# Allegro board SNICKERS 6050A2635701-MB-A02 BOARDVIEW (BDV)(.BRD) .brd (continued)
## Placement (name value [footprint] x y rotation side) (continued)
C6203  22uF_6.3V_5  [CSC_200X125X130_2]  167.19 155.16 0 bottom
C6204  22uF_6.3V_5_DY  [CSC_200X125X130_2]  167.2 156.78 0 bottom
C6210  10UF_25V_5  [CSC_200X125X140_2]  150.15 160.51 270 bottom
C6211  0.1uF_25V_2  [CSC_100X050X040_2]  151.42 160.89 270 bottom
C6215  0.1uF_16V_2  [CSC_100X050X040_2]  156.5 154.29 270 bottom
C6216  1uF_6.3V_2  [CSC_100X050X040_2]  154.08 156.32 90 bottom
C6217  0.01uF_50V_2  [CSC_100X050X040_2]  153.19 156.32 90 bottom
C6240  10uF_6.3V_3  [CSC_160X080X080_2]  171.1 155.94 90 bottom
C6241  10uF_6.3V_3  [CSC_160X080X080_2]  172.14 150.11 270 bottom
C6242  1uF_6.3V_2  [CSC_100X050X040_2]  176.44 150.62 180 bottom
C6243  1uF_6.3V_2  [CSC_100X050X040_2]  175.67 155.05 180 bottom
C6300  22uF_6.3V_5  [CSC_200X125X130_2]  137.32 96.43 0 bottom
C6301  22uF_6.3V_5  [CSC_200X125X130_2]  137.32 93.23 0 bottom
C6302  22uF_6.3V_5  [CSC_200X125X130_2]  137.32 94.83 0 bottom
C6303  22uF_6.3V_5  [CSC_200X125X130_2]  137.32 98.03 0 bottom
C6304  22uF_6.3V_5_DY  [CSC_200X125X130_2]  137.32 99.63 0 bottom
C6310  10UF_25V_5  [CSC_200X125X140_2]  126.5 101.71 0 bottom
C6311  0.1uF_25V_2  [CSC_100X050X040_2]  126.27 102.98 0 bottom
C6315  0.1uF_16V_2  [CSC_100X050X040_2]  127.67 94.6 90 bottom
C6316  1uF_6.3V_2  [CSC_100X050X040_2]  123.6 94.73 90 bottom
C6317  0.01uF_50V_2  [CSC_100X050X040_2]  122.71 94.73 90 bottom
C6350  22uF_6.3V_5  [CSC_200X125X130_2]  103.28 135.75 270 bottom
C6352  CSC0402_DY  [CSC_100X050X040_2]  103.92 143.5 180 top
C6360  10uF_6.3V_3  [CSC_160X080X080_2]  101.25 147.69 180 top
C6450  22uF_6.3V_5  [CSC_200X125X130_2]  254.41 84.06 180 top
C6452  CSC0402_DY  [CSC_100X050X040_2]  246.54 82.54 90 top
C6460  10uF_6.3V_3  [CSC_160X080X080_2]  249.33 82.79 270 top
C6610  10UF_25V_5  [CSC_200X125X140_2]  238.28 71.74 180 bottom
C6611  10UF_25V_5  [CSC_200X125X140_2]  238.28 73.39 180 bottom
C6613  CSC0402_DY  [CSC_100X050X040_2]  223.3 78.32 270 bottom
C6614  CSC0402_DY  [CSC_100X050X040_2]  223.3 79.97 90 bottom
C6615  0.1uF_16V_2  [CSC_100X050X040_2]  240.44 65.64 180 bottom
C6616  1uF_10V_2  [CSC_100X050X040_2]  234.73 64.12 180 bottom
C6617  0.1uF_25V_2  [CSC_100X050X040_2]  226.98 78.98 90 bottom
C6618  CSC0402_DY  [CSC_100X050X040_2]  226.09 78.98 90 bottom
C6639  0.0015uF_50V_2  [CSC_100X050X040_2]  226.09 85.58 270 bottom
C6640  CSC0402_DY  [CSC_100X050X040_2]  227.77 82.94 0 bottom
C6641  CSC0402_DY  [CSC_100X050X040_2]  230.28 86.85 90 bottom
C6642  1uF_6.3V_2  [CSC_100X050X040_2]  233.82 81.52 0 bottom
C6643  1uF_6.3V_2  [CSC_100X050X040_2]  228.38 86.85 90 bottom
C6644  0.33uF_10V_3  [CSC_160X080X080_2]  228.89 82.66 0 top
C6645  4700pF_50V_2  [CSC_100X050X040_2]  229.78 74.15 270 bottom
C6646  1000PF_50V_2  [CSC_100X050X055_2]  228.51 76.06 0 bottom
C6699  15uF_25V  [CS_350X280X200_2]  244.13 77.96 0 bottom
C6900  0.22uF_6.3V_2  [CSC_100X050X040_2]  283.12 131.68 90 top
C6902  3900pF_16V_2  [CSC_100X050X040_2]  65.82 89.65 90 top
C6906  CSC0402_DY  [CSC_100X050X040_2]  294.67 137.53 270 top
C6998  0.22uF_6.3V_2  [CSC_100X050X040_2]  293.02 128.64 270 top
C6999  100pF_50V_2  [CSC_100X050X040_2]  294.04 133.21 90 top
C7001  1uF_6.3V_2  [CSC_100X050X040_2]  301.28 127.37 270 top
C7035  CSC0402_DY  [CSC_100X050X040_2]  97.44 143.24 180 top
C7036  CSC0402_DY  [CSC_100X050X040_2]  210.22 147.18 90 top
C7037  CSC0402_DY  [CSC_100X050X040_2]  117.13 96 90 top
C7050  10uF_6.3V_3  [CSC_160X080X080_2]  117.25 83.68 270 bottom
C7100  10uF_6.3V_3  [CSC_160X080X080_2]  303.31 109.59 0 top
C7110  0.1uF_16V_2  [CSC_100X050X040_2]  211.11 149.97 90 bottom
C7152  CSC0402_DY  [CSC_100X050X040_2]  139.73 103.62 180 bottom
C7153  10uF_6.3V_3  [CSC_160X080X080_2]  136.43 91.17 90 bottom
C7352  10uF_6.3V_3  [CSC_160X080X080_2]  109.38 84.69 270 bottom
C7355  10uF_6.3V_3  [CSC_160X080X080_2]  307.25 115.94 90 top
C7400  0.1uF_16V_2  [CSC_100X050X040_2]  239.94 109.97 90 top
C7401  3300pF_50V_2  [CSC_100X050X040_2]  243.24 100.44 90 top
C7402  1000PF_50V_2  [CSC_100X050X055_2]  241.41 100.44 90 top
C7403  3300pF_50V_2  [CSC_100X050X040_2]  243.24 112.25 90 top
C7455  82pF_50V_2  [CSC_100X050X040_2]  116.87 126.48 0 top
C7456  0.1uF_25V_2  [CSC_100X050X040_2]  116.87 125.46 0 top
C7457  68pF_50V_2_DY  [CSC_100X050X040_2]  274.23 118.48 180 top
C7458  82pF_50V_2  [CSC_100X050X040_2]  274.23 117.59 180 top
C7459  68pF_50V_2_DY  [CSC_100X050X040_2]  195.23 60.82 0 top
C7460  82pF_50V_2_DY  [CSC_100X050X040_2]  195.87 59.93 0 top
C7461  68pF_50V_2_DY  [CSC_100X050X040_2]  224.57 54.47 90 top
C7462  82pF_50V_2_DY  [CSC_100X050X040_2]  225.46 54.47 90 top
C7463  68pF_50V_2_DY  [CSC_100X050X040_2]  223.81 68.57 270 top
C7464  82pF_50V_2_DY  [CSC_100X050X040_2]  222.92 68.57 270 top
C7465  68pF_50V_2_DY  [CSC_100X050X040_2]  196.37 67.8 0 bottom
C7466  82pF_50V_2_DY  [CSC_100X050X040_2]  196.37 68.69 0 bottom
C7467  68pF_50V_2  [CSC_100X050X040_2]  256.95 144.89 180 top
C7468  82pF_50V_2  [CSC_100X050X040_2]  142.65 160.64 0 top
C7469  68pF_50V_2_DY  [CSC_100X050X040_2]  162.34 158.86 0 bottom
C7470  82pF_50V_2_DY  [CSC_100X050X040_2]  168.69 150.61 180 bottom
C7471  68pF_50V_2_DY  [CSC_100X050X040_2]  136.68 101.33 270 bottom
C7472  68pF_50V_2  [CSC_100X050X040_2]  118.65 99.05 90 bottom
C7473  82pF_50V_2  [CSC_100X050X040_2]  119.54 99.43 90 bottom
C7474  82pF_50V_2_DY  [CSC_100X050X040_2]  135.67 101.33 270 bottom
C7475  CSC0402_DY  [CSC_100X050X040_2]  156.62 86.73 90 bottom
C7476  CSC0402_DY  [CSC_100X050X040_2]  163.35 106.69 90 top
C7478  CSC0402_DY  [CSC_100X050X040_2]  162.47 106.69 90 top
C7485  4.7uF_6.3V_3_DY  [CSC_160X080X080_2]  126.65 130.8 0 top
C7486  4.7uF_6.3V_3_DY  [CSC_160X080X080_2]  169.32 148.7 180 bottom
C7487  2.2uF_6.3V_2  [CSC_100X050X040_2]  169.32 149.72 0 bottom
C7488  CSC0402_DY  [CSC_100X050X040_2]  173.51 85.2 90 top
C7490  82pF_50V_2  [CSC_100X050X040_2]  213.52 156.96 90 bottom
C7491  82pF_50V_2  [CSC_100X050X040_2]  249.97 149.08 180 bottom
C7494  2.2uF_6.3V_2_DY  [CSC_100X050X040_2]  173.51 56.12 180 top
C7495  82pF_50V_2  [CSC_100X050X040_2]  239.55 78.47 90 bottom
C7500  100pF_50V_2  [CSC_100X050X040_2]  155.38 63.74 180 bottom
C7501  100pF_50V_2  [CSC_100X050X040_2]  155.25 66.41 180 bottom
C7502  0.1uF_25V_2  [CSC_100X050X040_2]  137.07 65.14 180 top
C7503  100pF_50V_2  [CSC_100X050X040_2]  147.23 65.26 90 bottom
C7520  0.1uF_16V_2  [CSC_100X050X040_2]  314.23 82.15 270 top
C7521  0.1uF_16V_2  [CSC_100X050X040_2]  320.58 117.71 180 top
C7578  0.1uF_16V_2  [CSC_100X050X040_2]  315.37 16.37 90 top
C7579  0.1uF_16V_2  [CSC_100X050X040_2]  294.67 56.63 90 bottom
C7581  0.1uF_16V_2_DY  [CSC_100X050X040_2]  116.49 124.19 180 top
C7582  82pF_50V_2  [CSC_100X050X040_2]  142.65 152.56 180 top
C7583  0.1uF_16V_2_DY  [CSC_100X050X040_2]  132.37 113.4 180 top
C7584  0.1uF_16V_2_DY  [CSC_100X050X040_2]  156.62 77.33 90 top
C7585  0.1uF_16V_2_DY  [CSC_100X050X040_2]  239.3 63.87 270 top
C7586  0.1uF_16V_2_DY  [CSC_100X050X040_2]  228.12 96 180 top
C7587  0.1uF_16V_2_DY  [CSC_100X050X040_2]  281.21 123.43 90 top
C7588  0.1uF_16V_2_DY  [CSC_100X050X040_2]  245.65 56.37 270 bottom
C7589  0.1uF_16V_2_DY  [CSC_100X050X040_2]  303.3 110.62 0 top
C7591  0.1uF_16V_2_DY  [CSC_100X050X040_2]  180.37 82.79 0 top
C7592  0.1uF_16V_2_DY  [CSC_100X050X040_2]  316.59 21.45 270 top
C7593  0.1uF_16V_2_DY  [CSC_100X050X040_2]  289.21 93.08 270 top
C7594  82pF_50V_2  [CSC_100X050X040_2]  245.52 83.04 270 top
C7595  0.1uF_25V_2_DY  [CSC_100X050X040_2]  144.69 160.13 90 bottom
C7596  0.1uF_16V_2_DY  [CSC_100X050X040_2]  143.16 65.26 270 bottom
C7597  0.1uF_16V_2  [CSC_100X050X040_2]  218.73 144.64 0 bottom
C7598  0.1uF_16V_2  [CSC_100X050X040_2]  240.95 140.83 0 top
C7599  82pF_50V_2  [CSC_100X050X040_2]  248.83 146.16 0 bottom
C7600  CSC0402_DY  [CSC_100X050X040_2]  269.15 132.32 90 bottom
C7601  0.1uF_25V_2  [CSC_100X050X040_2]  269.91 115.43 180 top
C7602  0.1uF_25V_2  [CSC_100X050X040_2]  208.69 157.47 180 bottom
C7603  0.1uF_25V_2  [CSC_100X050X040_2]  125.38 113.78 0 top
C7604  0.1uF_16V_2  [CSC_100X050X040_2]  199.93 126.35 0 top
C7605  0.1uF_16V_2  [CSC_100X050X040_2]  143.8 133.46 180 top
C7606  0.1uF_16V_2  [CSC_100X050X040_2]  163.23 149.59 90 bottom
C7607  0.1uF_16V_2_DY  [CSC_100X050X040_2]  170.44 53.33 270 top
C7608  0.1uF_16V_2_DY  [CSC_100X050X040_2]  109.76 88.89 180 bottom
C7609  0.1uF_25V_2_DY  [CSC_100X050X040_2]  136.81 68.44 180 top
C7610  CSC0402_DY  [CSC_100X050X040_2]  197.26 159.88 180 bottom
C7611  0.1uF_25V_2_DY  [CSC_100X050X040_2]  129.7 112.76 90 top
C7612  0.1uF_16V_2_DY  [CSC_100X050X040_2]  188.63 74.28 180 top
C7613  0.1uF_16V_2_DY  [CSC_100X050X040_2]  315.63 73.14 270 top
C7614  0.1uF_16V_2_DY  [CSC_100X050X040_2]  308.39 116.7 90 top
C7615  CSC0402_DY  [CSC_100X050X040_2]  238.28 159.12 180 bottom
C7616  0.1uF_25V_2_DY  [CSC_100X050X040_2]  310.17 131.94 180 top
C7617  0.1uF_16V_2_DY  [CSC_100X050X040_2]  58.2 80.76 0 top
C7618  0.1uF_25V_2_DY  [CSC_100X050X040_2]  130.21 155.43 270 bottom
C7619  0.1uF_25V_2_DY  [CSC_100X050X040_2]  214.41 156.96 270 bottom
C7620  CSC0402_DY  [CSC_100X050X040_2]  155.23 150.48 180 bottom
C7621  0.1uF_25V_2  [CSC_100X050X040_2]  278.42 146.29 180 top
C7622  0.1uF_16V_2_DY  [CSC_100X050X040_2]  212 63.87 90 bottom
C7623  0.1uF_16V_2_DY  [CSC_100X050X040_2]  101.12 104.13 180 top
C7625  82pF_50V_2  [CSC_100X050X040_2]  187.1 162.04 0 top
C7627  0.1uF_16V_2  [CSC_100X050X040_2]  317.28 59.68 90 top
C7628  0.1uF_16V_2  [CSC_100X050X040_2]  316.01 38.47 0 top
C7629  0.1uF_16V_2  [CSC_100X050X040_2]  316.77 77.58 180 top
C7630  CSC0402_DY  [CSC_100X050X040_2]  133.26 101.84 0 bottom
C7631  0.1uF_16V_2  [CSC_100X050X040_2]  316.14 42.91 180 top
C7632  0.22uF_6.3V_2  [CSC_100X050X040_2]  225.2 130.67 270 top
C7633  0.22uF_6.3V_2  [CSC_100X050X040_2]  232.57 130.67 270 top
C7634  0.22uF_6.3V_2  [CSC_100X050X040_2]  213.52 144.77 270 top
C7635  0.22uF_6.3V_2  [CSC_100X050X040_2]  203.49 145.02 0 top
C7636  0.22uF_6.3V_2  [CSC_100X050X040_2]  184.06 145.15 180 top
C7637  0.22uF_6.3V_2  [CSC_100X050X040_2]  174.02 143.62 0 top
C7638  0.22uF_6.3V_2  [CSC_100X050X040_2]  147.99 146.29 180 top
C7639  0.22uF_6.3V_2  [CSC_100X050X040_2]  162.47 135.24 90 top
C7640  0.22uF_6.3V_2  [CSC_100X050X040_2]  149.13 135.62 90 top
C7641  0.1uF_25V_2  [CSC_100X050X040_2]  249.97 105.78 90 top
C7642  0.1uF_25V_2  [CSC_100X050X040_2]  238.28 78.47 270 bottom
C7643  0.1uF_25V_2  [CSC_100X050X040_2]  238.28 70.47 180 bottom
C7650  0.1uF_25V_2  [CSC_100X050X040_2]  275.37 115.17 0 bottom
C7654  CSC0402_DY  [CSC_100X050X040_2]  296.2 65.64 90 top
C7661  CSC0402_DY  [CSC_100X050X040_2]  231.93 66.53 270 top
C9000  0.1uF_16V_2  [CSC_100X050X040_2]  79.66 110.22 0 top
C9001  1uF_6.3V_2  [CSC_100X050X040_2]  79.66 111.11 0 top
C9002  0.1uF_16V_2  [CSC_100X050X040_2]  79.66 112.38 0 top
C9003  1uF_6.3V_2  [CSC_100X050X040_2]  79.66 113.27 0 top
C9004  1uF_6.3V_2  [CSC_100X050X040_2]  79.66 109.33 0 top
C9005  0.1uF_16V_2  [CSC_100X050X040_2]  79.66 114.16 0 top
C9006  0.1uF_16V_2  [CSC_100X050X040_2]  66.96 112.38 180 top
C9007  0.1uF_16V_2  [CSC_100X050X040_2]  79.66 115.56 0 top
C9009  1uF_6.3V_2  [CSC_100X050X040_2]  79.66 116.44 0 top
C9010  0.1uF_16V_2  [CSC_100X050X040_2]  75.72 120.13 90 top
C9011  1uF_6.3V_2  [CSC_100X050X040_2]  72.42 120.13 90 top
C9015  0.1uF_16V_2  [CSC_100X050X040_2]  71.53 136.64 0 top
C9021  1000PF_50V_2  [CSC_100X050X055_2]  71.79 143.5 0 top
C9035  1uF_6.3V_2  [CSC_100X050X040_2]  87.41 147.69 270 top
C9036  0.1uF_16V_2  [CSC_100X050X040_2]  73.82 157.97 270 top
C9113  0.1uF_16V_2  [CSC_100X050X040_2]  279.94 32.3 270 bottom
C9114  CSC0402_DY  [CSC_100X050X040_2]  286.67 118.73 0 top
CN200  ACES_51540_04041_001_40P  [FPC_ACES_40_050_R_180_1]  109.3 86.85 0 top
CN202  ENTERY_6712K_F08M_02L_8P  [SWBACK-6012B0275004-003]  191.05 56 0 top
CN290  ACES_50505_0064N_001_6P  [COMET-6012B0317701-002]  104.35 134.25 180 top
CN300  ACES_51510_0344N_001_34P  [FPC_ACES_34_080_R_200_1]  277.35 79.4 0 top
CN301  ENTERY_6712K_F08M_02L_8P  [SWBACK-6012B0275004-003]  300.35 82.95 0 top
CN365  ACES_91960_0084L_8P  [SWBACK-6026B0150101-002]  147.57 72.6 180 bottom
CN375  ACES_50238_02471_001_24P_DY  [GALIEO16-6012B0073604-003]  138.35 71.8 270 bottom
CN600  ACES_50376_01001_001_10P  [SWBACK-6012B0452401-001]  239.7 43.9 180 bottom
CN640  ACES_50271_0040N_001_4P  [WTB_ACES_4_125_SMD_R_M_340_1]  249.35 155.5 270 bottom
CN820  FULLINHOPE_A0131_0001_12P  [SD_FULLP_12_SMD_RV_455]  314.4 64.7 270 bottom
CN1300  FOXCONN_AS0BC26_S30BE_7H_75P  [MPCI_FOX_75_050_RV_300]  310.02 119.9 270 bottom
CN1400  LOTES_APCI0018_P005A_75P  [MPCI_LOTES_75_050_RV_300]  252.68 66 90 bottom
CN1451  TAI_PMPAT3_08GLBS7N14N0_9P  [SIM_TAIT_9_ST_150-001]  250.35 68.8 0 top
CN1700  ALLTOP_C11848_122A1_L_22P  [SWBACK-6012B0520601-005]  88.74 79.8 180 bottom
CN1951  LOTES_APCI0020_P001A01_75P  [MPCI_LOTES_75_050_ST_300]  298.85 93.3 270 bottom
CN2200  ACES_50505_0064N_001_6P  [COMET-6012B0317701-002]  285.6 57 90 top
CN2400  SINGA_2UB4006_180101F_9P  [USB3_SIGAT_9_DIP_SS_S_240_526]  318.6 68.75 90 top
CN2401  SINGA_2UB4006_180101F_9P  [USB3_SIGAT_9_DIP_SS_S_240_526]  318.6 50.25 90 top
CN2500  SINGA_2UB4006_180101F_9P  [USB3_SIGAT_9_DIP_SS_S_240_526]  40.3 43.85 270 top
CN3000  ACES_59003_04006_001_40P  [SWBACK-6012B0522301-001]  110.85 116 90 bottom
CN3050  SYN_070546HR015M22BZR_15P  [SWBACK-6012B0334801-002]  33.5 70.85 90 bottom
CN3300  TAIWIN_DP004_206CRL_TW_20P  [SWBACK-6012B0519601-001]  321.05 29.95 90 top
CN3601  FOX_QL1046L_D262AR_7H_92P  [DOCK_FOX_94_050_DIP_440]  323.8 119 270 bottom
CN4100  FOX_AS0A626_U4R6_7H_HP_204P  [DDR3_FOX_204_RV_400_4]  231.35 138.5 0 bottom
CN4125  FOX_AS0A626_U4R6_7H_HP_204P  [DDR3_FOX_204_RV_400_4]  154.35 138.5 0 bottom
CN4300  ACES_50271_0040N_001_4P  [WTB_ACES_4_125_SMD_R_M_340_1]  109.35 155.5 90 bottom
CN4750  ENTERY_3703K_Q02N_11L_2P  [WTB_ENTRY_2_100_SMD_R_M_295]  268.35 148.5 0 top
CN4920  SAMTEC_BSH_030_01_L_D_A_TR_60P  [BTB_SAM_60_050_F_325]  231.86 83.27 90 top
CN4941  ACES_50501_0184N_001_18P_DY  [FPC_ACES_18_050_R_200_1]  133.51 78.33 90 top
CN6050  FOX_BP02083_B24B1_9H_8P  [AEROSMIT-6012B0335005-002]  145.45 61 180 bottom
CN9000  ACES_51540_04041_001_40P  [FPC_ACES_40_050_R_180_1]  81.25 104.6 0 top
CN9001  HAMB_083AA24F08B_10P  [SMART_CONCT_10_ST_S_255]  49.39 131.5 90 bottom
CN9002  ACES_51548_01541_001_15P  [FPC_ACES_15_050_R_200]  81.65 157.1 0 top
CN9021  ENTERY_6712K_F08M_02L_8P  [SWBACK-6012B0275004-003]  72.85 149.1 90 top
CN9100  ACES_50505_0064N_001_6P  [COMET-6012B0317701-002]  282 33.35 90 top
D100  DIODE-BAT54-TAP-PHP_DY  [DSSOT23_292X130X109_3_095]  289.34 119.11 0 top
D110  EVL_23_22B_Y2ST3D_C30_2T_4P  [LED_EVERL_V_D_320X125X110]  308.1 156.3 0 top
D126  EVL_23_22B_Y2ST3D_C30_2T_4P  [LED_EVERL_V_D_320X125X110]  320.5 156.3 0 top
D301  PANASONIC_DB3X313J0L_SOT_3P  [DSSOT23_290X150X140_3_095]  286.67 92.44 0 top
D302  BAW56S  [DSSOT363_200X125X110_6_065]  286.54 88.63 0 top
D303  BAW56S  [DSSOT363_200X125X110_6_065]  284.13 88.63 0 top
D304  BAW56S  [DSSOT363_200X125X110_6_065]  281.72 88.63 0 top
D485  PHP_PESD5V0S1BB_SOD523_2P  [DSSOD523_120X080X065_2-2]  312.96 85.2 270 top
D486  PHP_PESD5V0S1BB_SOD523_2P  [DSSOD523_120X080X065_2-2]  312.58 102.86 90 top
D500  PANASONIC_DB3X313J0L_SOT_3P  [DSSOT23_290X150X140_3_095]  289.03 65.52 180 top
D501  PANASONIC_DB3X313J0L_SOT_3P  [DSSOT23_290X150X140_3_095]  293.73 61.33 0 top
D801  PANASONIC_DB3X313J0L_SOT_3P  [DSSOT23_290X150X140_3_095]  294.42 76.44 90 top
D1300  BAT54_30V_0.2A  [TSOT23_290X130X110_3_096_P1]  312.71 122.08 90 top
D1410  BAT54_30V_0.2A  [TSOT23_290X130X110_3_096_P1]  262.54 66.79 180 top
D1451  DIODES_BAV99  [DSMI_3A]  258.48 80.25 0 top
D2201  PHP_PESD5V2S2UT_SOT23_3P_DY  [DSOT23_290X130X110_3_095]  279.05 53.33 90 top
D2551  PANASONIC_DB3X313J0L_SOT_3P_DY  [DSSOT23_290X150X140_3_095]  261.53 60.06 0 top
D2951  PANASONIC_DB3X313J0L_SOT_3P  [DSSOT23_290X150X140_3_095]  246.41 111.52 270 top
D3000  BAT54_30V_0.2A  [TSOT23_290X130X110_3_096_P1]  107.6 119.11 90 top
D4200  SFI0402_050E3R0PP_LF_DY  [DS_100X050X060_2_S2]  257.08 142.23 270 top
D4201  SFI0402_050E3R0PP_LF_DY  [DS_100X050X060_2_S2]  185.83 143.62 180 top
D4202  SFI0402_050E3R0PP_LF_DY  [DS_100X050X060_2_S2]  209.96 144.77 90 top
D4203  SFI0402_050E3R0PP_LF_DY  [DS_100X050X060_2_S2]  143.03 146.54 90 bottom
D4204  SFI0402_050E3R0PP_LF_DY  [DS_100X050X060_2_S2]  200.44 131.56 180 top
D4205  SFI0402_050E3R0PP_LF_DY  [DS_100X050X060_2_S2]  170.34 146.8 180 top
D4750  BAT54C  [DSSOT23_290X130X105_3_095]  142.4 103.36 90 bottom
D6015  PANJTT_PJSOT24C_SOT23_3P  [DSOT23_292X130X110_3_095]  312.59 141.02 270 top
D6016  BAT54C  [DSSOT23_290X130X105_3_095]  283.37 123.05 180 top
D6017  BAT54C  [DSSOT23_290X130X105_3_095]  298.99 144 270 top
D6018  1SS355VMTE_17  [TOOTSIE-6011B0129301-005]  290.98 132.15 270 top
D6019  B0530W_7  [DSSOD123_270X155X135_2]  137.19 66.91 180 top
D6150  DIODES_BAV99  [DSMI_3A]  224.96 150.2 270 bottom
D6151  DIODES_BAV99  [DSMI_3A]  219.78 151.37 90 bottom
D6901  BZT52-B4V7S_DY  [DSOD323_185X125X095_2_231]  55.02 84.69 270 top
D7400  PANASONIC_DB3X313J0L_SOT_3P  [DSSOT23_290X150X140_3_095]  244.76 106.16 0 top
D7504  PHP_PESD5V0S1BB_SOD523_2P_DY  [DSSOD523_120X080X065_2-2]  155.35 65.01 180 bottom
D7505  PHP_PESD5V0S1BB_SOD523_2P_DY  [DSSOD523_120X080X065_2-2]  155.35 67.68 180 bottom
D7506  PHP_PESD5V0S1BB_SOD523_2P_DY  [DSSOD523_120X080X065_2-2]  155.35 69.33 180 bottom
D7600  SFI0402_050E3R0PP_LF  [DS_100X050X060_2_S2]  284.13 134.73 90 top
D7601  SFI0402_050E3R0PP_LF  [DS_100X050X060_2_S2]  111.92 162.04 0 bottom
D7602  SFI0402_050E3R0PP_LF  [DS_100X050X060_2_S2]  186.72 159.75 180 bottom
D7603  SFI0402_050E3R0PP_LF  [DS_100X050X060_2_S2]  250.48 146.16 0 bottom
D7604  SFI0402_050E3R0PP_LF  [DS_100X050X060_2_S2]  143.29 150.61 0 bottom
D7605  SFI0402_050E3R0PP_LF  [DS_100X050X060_2_S2]  303.18 126.48 90 top
D7606  SFI_SFI0603_240E2R5PP_LF_2P  [DS_160X080X090_2]  144.94 157.08 0 bottom
D7607  SFI_SFI0603_240E2R5PP_LF_2P  [DS_160X080X090_2]  254.03 145.78 0 top
D7608  SFI_SFI0603_240E2R5PP_LF_2P  [DS_160X080X090_2]  211.74 158.86 180 bottom
D7609  SFI_SFI0603_240E2R5PP_LF_2P  [DS_160X080X090_2]  122.59 155.05 90 bottom
D7610  SFI_SFI0603_240E2R5PP_LF_2P  [DS_160X080X090_2]  215.42 156.58 90 bottom
D7611  SFI_SFI0603_240E2R5PP_LF_2P  [DS_160X080X090_2]  162.21 149.59 270 bottom
D7612  SFI_SFI0603_240E2R5PP_LF_2P  [DS_160X080X090_2]  146.46 145.15 0 top
D7613  SFI_SFI0603_240E2R5PP_LF_2P  [DS_160X080X090_2]  199.93 127.49 180 top
D7614  SFI_SFI0603_240E2R5PP_LF_2P  [DS_160X080X090_2]  232.57 127.87 270 top
D7615  SFI_SFI0603_240E2R5PP_LF_2P  [DS_160X080X090_2]  194.6 87.23 90 top
D7616  SFI_SFI0603_240E2R5PP_LF_2P  [DS_160X080X090_2]  214.54 144.38 90 top
D7617  SFI_SFI0603_240E2R5PP_LF_2P  [DS_160X080X090_2]  194.6 80.38 180 top
D7618  SFI_SFI0603_240E2R5PP_LF_2P  [DS_160X080X090_2]  208.44 68.06 180 bottom
D7619  SFI_SFI0603_240E2R5PP_LF_2P  [DS_160X080X090_2]  228.63 149.41 0 bottom
D7620  SFI_SFI0603_240E2R5PP_LF_2P  [DS_160X080X090_2]  188.78 151.62 0 bottom
D7621  SFI_SFI0603_240E2R5PP_LF_2P  [DS_160X080X090_2]  187.48 73.14 0 top
D9030  EVL_12_22_Y2ST3D_C30_2C_3P  [LED_EVERL_R_D_300X200X100_2]  41.59 159.8 180 top
D9031  EVL_12_21_T3D_CP1Q2B12Y_2C_2P  [ST133ID-6011B0115101-001]  31.71 159.8 180 top
D9032  EVL_12_22_Y2ST3D_C30_2C_3P  [LED_EVERL_R_D_300X200X100_2]  36.65 159.8 180 top
D9033  EVL_12_22_Y2ST3D_C30_2C_3P  [LED_EVERL_R_D_300X200X100_2]  26.77 159.8 180 top
D9100  19_217_W1D_AP1Q2QY_3T  [LED_EVERLI_V_S_160X080X040]  265.1 26.35 0 bottom
FIX1  -  [FIX_MASK]  32.8 85.71 0 top
FIX2  -  [FIX_MASK]  105.44 157.97 0 top
FIX3  -  [FIX_MASK]  321.72 158.91 0 top
FIX4  -  [FIX_MASK]  316.39 7.73 0 top
FIX5  -  [FIX_MASK]  325.28 3.92 180 bottom
FIX6  -  [FIX_MASK]  321.85 157.97 180 bottom
FIX7  -  [FIX_MASK]  105.57 160.77 180 bottom
FIX8  -  [FIX_MASK]  61.12 80.5 180 bottom
FIX600  -  [FIX_MASK]  201.05 46.34 180 bottom
FIX601  -  [FIX_MASK]  232.55 43.42 180 bottom
FIX602  -  [FIX_MASK]  214.52 45.96 180 bottom
FIX9000  -  [FIX_MASK]  3.91 103.36 180 bottom
FIX9001  -  [FIX_MASK]  3.91 153.02 180 bottom
FIX9002  -  [FIX_MASK]  87.15 156.58 180 bottom
FIX9003  -  [FIX_MASK]  89.95 104 180 bottom
FIX9004  -  [FIX_MASK]  3.91 153.02 0 top
FIX9005  -  [FIX_MASK]  3.91 103.36 0 top
FIX9006  -  [FIX_MASK]  57 158.1 0 top
FIX9007  -  [FIX_MASK]  91.7 111.54 0 top
FIX9100  -  [FIX_MASK]  284.39 36.74 0 bottom
FIX9101  -  [FIX_MASK]  260.89 31.03 0 bottom
FIX9102  -  [FIX_MASK]  260.89 31.03 180 top
JACK485  FOX_JM3611_SP51AB11_7H_12P  [RJ45_FOX_12_DIP_RS_Y_510]  321.35 88.7 90 top
JACK600  SINGA_2SJ3005_023111F_7P  [AUDIO_SIGAT_7_R_265_540]  327.95 9 90 top
JACK6000  SINGA_2DC3092_000111F_9P  [DC_SIGAT_3_R_145_358]  321.15 144.8 270 bottom
L400  SWF2520CF_4R7K_M  [STRIKE-6014B0099601-002]  292.13 103.62 0 top
L502  BLM18PG600SN1D  [EMIS_BLM11]  301.02 70.22 270 top
L550  BLM18PG600SN1D  [EMIS_BLM11]  312.33 53.33 270 top
L551  BLM18PG600SN1D  [EMIS_BLM11]  309.4 54.34 180 top
L602  BLM18PG600SN1D  [EMIS_BLM11]  322.61 9.13 180 bottom
L603  BLM15AG121SN1D_500mA  [LS_100X050X055_2]  238.03 47.36 180 bottom
L1400  WCM_2012_900T  [LS_200X120X120_4]  244.89 70.64 270 bottom
L2400  WCM_2012_900T  [LS_200X120X120_4]  312.8 70.02 0 top
L2404  WCM_2012_900T  [LS_200X120X120_4]  315.12 54.47 270 top
L2500  WCM_2012_900T  [LS_200X120X120_4]  42.2 52.94 90 top
L2550  SWF2520CF_4R7K_M  [STRIKE-6014B0099601-002]  280.83 61.45 180 top
L3000  WCM_2012_900T  [LS_200X120X120_4]  115.93 122.54 180 top
L3001  WCM_2012_900T  [LS_200X120X120_4]  123.1 103.11 90 top
L3051  HCI1005F_R12J_M  [LS_100X050X060_2]  38.26 65.39 180 top
L3052  HCI1005F_R12J_M  [LS_100X050X060_2]  38.26 67.68 180 top
L3053  HCI1005F_R12J_M  [LS_100X050X060_2]  38.26 70.09 180 top
L3065  BLM15BB470SN1D  [LS_100X050X060_2]  94.14 90.41 180 bottom
L3066  BLM15BB470SN1D_DY  [LS_100X050X060_2]  89.06 83.42 0 bottom
L3067  BLM15BB470SN1D  [LS_100X050X060_2]  90.97 91.72 90 bottom
L3068  SWF2520CF_4R7K_M  [STRIKE-6014B0099601-002]  92.4 89.31 270 top
L4850  2.2uH_20%  [LS_160X080X100_2]  186.6 71.99 180 top
L4851  2.2uH_20%  [LS_160X080X100_2]  159.67 63.87 270 bottom
L4854  2.2uH_20%  [LS_160X080X100_2]  161.07 63.87 270 bottom
L4865  2.2uH_20%  [LS_160X080X100_2]  163.1 64.88 0 bottom
L6000  ETQP3W4R7WFN  [LS_700X660X300_2_555]  273.41 126.86 90 bottom
L6035  NFE31PT222Z1E9L  [EMIS_NFM60R]  306.59 142.01 0 top
L6100  PCMC063T-1R5MN  [OBERONC-6014B0026101-006]  197.89 155.03 180 bottom
L6150  PCMC063T-1R5MN  [OBERONC-6014B0026101-006]  238.88 154.42 180 bottom
L6200  PAN_ETQP3W1R0WFN_4P  [LS_700X660X300_4]  161.7 154.44 0 bottom
L6300  PAN_ETQP3W1R0WFN_4P  [LS_700X660X300_4]  131.6 97.65 0 bottom
L6350  NRS5020T1R0NMGJ  [LS_500X500X200_2_340]  98.97 139.94 270 bottom
L6450  NRS5020T1R0NMGJ  [LS_500X500X200_2_340]  252.64 87.87 0 top
L6610  PCME063T-R24MS1R195  [COMET-6014B0228601-001]  230.16 67.75 180 bottom
MIC600  KNOWLES_SPK0415HM4H_B_8P  [MICP_KNOW_8_106]  194.54 45.5 270 bottom
MIC601  KNOWLES_SPK0415HM4H_B_8P  [MICP_KNOW_8_106]  246.46 45.5 90 bottom
NOREF  -  []  172.12 120.25 0 top
NOREF#2  -  []  -3.27 180.96 0 top
NOREF#3  -  []  268.64 34.91 0 top
NOREF#4  -  []  213.39 44.31 0 top
NOREF#5  -  []  226.2 43.54 0 top
NOREF#6  -  []  259.37 26.02 0 top
NOREF#7  -  []  264.45 29.58 0 top
NOREF#8  -  []  163.61 113.65 0 top
NOREF#9  -  []  184.56 117.33 0 top
NOREF#10  -  []  110.35 165 0 bottom
NOREF#11  -  []  207.55 45.32 180 bottom
NOREF#12  -  []  45.65 58.45 270 bottom
NOREF#13  -  [unnamed#2]  331.15 -83.5 180 bottom
NOREF#14  -  []  282.65 155.5 0 bottom
NOREF#15  -  []  273.64 27.65 270 bottom
NOREF#16  -  [unnamed#3]  32.45 57 180 bottom
NOREF#17  -  [unnamed#4]  16.85 168.51 180 bottom
NOREF#18  -  [unnamed#2]  321.15 166 180 bottom
NOREF#19  -  []  190.35 165 0 bottom
NOREF#20  -  [unnamed#2]  12.5 89.5 180 bottom
NOREF#21  -  []  39.65 33 180 bottom
NOREF#22  -  []  114.9 76.25 180 bottom
NOREF#23  -  [unnamed#2]  60.45 38.65 180 bottom
NOREF#24  -  [unnamed#5]  201 41.3 0 bottom
NOREF#25  -  []  195.34 49.48 180 bottom
NOREF#26  -  []  74.85 162.8 0 bottom
NOREF#27  -  [unnamed#2]  323.65 -7 180 bottom
NOREF#28  -  [unnamed#6]  255.7 27.35 180 bottom
NOREF#29  -  [unnamed#4]  319.3 -85.87 180 bottom
NOREF#30  -  []  254.35 165 0 bottom
NOREF#31  -  []  157.13 96.86 180 bottom
NOREF#32  -  [unnamed#7]  194.65 42.3 180 bottom
NOREF#33  -  []  66.95 93.1 0 bottom
NOREF#34  -  []  296.5 49.5 0 bottom
NOREF#35  -  [unnamed#2]  246.5 42.3 180 bottom
NOREF#36  -  [unnamed#2]  65.85 65.1 180 bottom
NOREF#37  -  []  309.53 166.36 180 bottom
NOREF#38  -  [unnamed#2]  275.7 43.85 180 bottom
NOREF#39  -  []  46.59 100 270 bottom
NOREF#40  -  []  19.62 -87.49 90 bottom
NOREF#41  -  [unnamed#2]  5 166 180 bottom
NOREF#42  -  [unnamed#6]  274.2 38.05 180 bottom
NOREF#43  -  []  174.44 49.51 180 bottom
NOREF#44  -  []  3.51 98.5 270 bottom
NOREF#45  -  []  251.5 28.35 90 bottom
NOREF#46  -  []  3.33 142.35 270 bottom
NOREF#47  -  []  17.56 -84.22 180 bottom
NOREF#48  -  []  265.35 49.5 180 bottom
NOREF#49  -  []  78.3 100 270 bottom
NOREF#50  -  []  4.6 142.61 270 bottom
NOREF#51  -  [unnamed#8]  324.95 101 180 bottom
NOREF#52  -  []  2.32 128.64 270 bottom
NOREF#53  -  [unnamed#2]  9.5 -83.5 180 bottom
NOREF#54  -  []  28.85 88.47 0 bottom
NOREF#55  -  [unnamed#6]  42.64 101 0 bottom
NOREF#56  -  []  54.63 76.25 180 bottom
NOREF#57  -  []  325.05 -1 0 bottom
NOREF#58  -  []  248.4 39.98 270 bottom
NOREF#59  -  [unnamed#2]  326.65 166 180 bottom
NOREF#60  -  []  204.36 40.34 270 bottom
NOREF#61  -  []  262.15 22.35 0 bottom
NOREF#62  -  [unnamed#2]  270.3 17.4 180 bottom
NOREF#63  -  []  324.86 162 0 bottom
NOREF#64  -  []  93.35 139 270 bottom
NOREF#65  -  []  230.34 49.5 90 bottom
NOREF#66  -  []  270 39.05 90 bottom
NOREF#67  -  []  11.35 163.7 0 bottom
PAD300  -  [POWERPAD_2_0610]  253.4 91.81 90 top
PAD310  POWERPAD1x1m  [POWERPAD1X1M]  284.77 100.82 180 top
PAD1411  POWERPAD1x1m  [POWERPAD1X1M]  258.99 79.74 90 bottom
PAD1700  -  [POWERPAD_2_0610]  99.85 83.3 90 bottom
PAD1950  -  [POWERPAD_2_0610]  292.64 86.73 270 top
PAD2990  -  [POWERPAD_2_0610_NSP]  139.99 84.57 90 bottom
PAD6010  -  [POWERPAD_2_0610]  269.91 115.94 0 bottom
PAD6100  -  [POWERPAD_2_0610]  192.19 150.83 270 bottom
PAD6110  -  [POWERPAD_2_0610]  211.28 156.45 270 bottom
PAD6150  -  [POWERPAD_2_0610]  228.99 158.78 90 bottom
PAD6160  -  [POWERPAD_2_0610]  247.25 147.94 180 bottom
PAD6200  -  [POWERPAD_2_0610]  166.02 149.97 270 bottom
PAD6210  -  [POWERPAD_2_0610]  146.97 159.88 90 bottom
PAD6240  POWERPAD1x1m  [POWERPAD1X1M]  170.97 153.27 270 bottom
PAD6241  POWERPAD1x1m  [POWERPAD1X1M]  178.47 150.23 90 bottom
PAD6242  -  [POWERPAD1X1M_NSP]  182.28 152.13 270 bottom
PAD6300  -  [POWERPAD_2_0610]  133.89 92.19 270 bottom
PAD6310  -  [POWERPAD_2_0610]  123.02 102.45 0 bottom
PAD6350  -  [POWERPAD_2_0610]  97.57 136.51 270 bottom
PAD6360  -  [POWERPAD_2_0610]  106.13 145.15 90 top
PAD6450  -  [POWERPAD_2_0610]  256.83 83.98 0 top
PAD6460  -  [POWERPAD_2_0610]  251.92 83.22 180 top
PAD6610  -  [POWERPAD_2_0610]  241.59 75.3 270 bottom
Q110  L2N7002WT1G  [TSSOT323_200X125X100_3_065]  307.5 149.97 90 top
Q112  L2N7002WT1G  [TSSOT323_200X125X100_3_065]  126.71 82.81 0 bottom
Q113  L2N7002WT1G_DY  [TSSOT323_200X125X100_3_065]  286.42 114.41 270 top
Q114  PM513BA_DY  [TSOT23_292X130X120_3_095]  283.24 116.85 180 top
Q115  L2N7002WT1G  [TSSOT323_200X125X100_3_065]  110.14 143.5 270 top
Q125  L2N7002DW1T1G  [TSSC88_200X125X110_6_065-2]  313.85 149.85 270 top
Q300  PM513BA  [TSOT23_292X130X120_3_095]  293.15 95.11 180 top
Q301  L2N7002WT1G  [TSSOT323_200X125X100_3_065]  290.23 95.11 180 top
Q302  L2N7002WT1G  [TSSOT323_200X125X100_3_065]  141.51 97.9 0 top
Q320  L2N7002DW1T1G  [TSSC88_200X125X110_6_065-2]  278.04 90.16 0 top
Q485  LES_LBSS84LT1G_SOT23_3P  [TSSOT23_292X130X111_3_095]  312.45 106.03 270 top
Q486  PDTC144EU  [TSOT323_200X125X110_3_065]  314.48 108.57 90 top
Q487  LMBT3904LT1G  [TSSOT23_292X130X111_3_096]  297.42 116.19 270 top
Q501  L2N7002WT1G  [TSSOT323_200X125X100_3_065]  280.19 54.21 270 bottom
Q528  L2N7002DW1T1G  [TSSC88_200X125X110_6_065-2]  296.7 54.85 180 top
Q600  L2N7002WT1G  [TSSOT323_200X125X100_3_065]  293.28 55.1 0 top
Q800  L2N7002WT1G  [TSSOT323_200X125X100_3_065]  284.51 60.18 0 bottom
Q801  PM514BA  [TSOT23_292X130X120_3_095]  287.31 60.69 0 bottom
Q802  L2N7002WT1G  [TSSOT323_200X125X100_3_065]  290.48 79.74 180 bottom
Q1000  L2N7002WT1G_DY  [TSSOT323_200X125X100_3_065]  237.4 107.05 0 top
Q1001  L2N7002WT1G_DY  [TSSOT323_200X125X100_3_065]  234.98 107.05 0 top
Q1002  L2N7002WT1G_DY  [TSSOT323_200X125X100_3_065]  232.57 107.05 0 top
Q1003  LES_LBSS84LT1G_SOT23_3P  [TSSOT23_292X130X111_3_095]  227.87 98.28 270 top
Q1300  FDC638APZ  [TSOT_290X160X110_6_095]  306.61 128.51 180 top
Q1301  L2N7002WT1G  [TSSOT323_200X125X100_3_065]  313.75 126.99 270 top
Q1302  L2N7002DW1T1G  [TSSC88_200X125X110_6_065-2]  313.21 110.98 90 top
Q1304  L2N7002WT1G  [TSSOT323_200X125X100_3_065]  309.71 124.19 90 top
Q1400  FDC638APZ_DY  [TSOT_290X160X110_6_095]  255.81 78.73 90 bottom
Q1401  L2N7002WT1G_DY  [TSSOT323_200X125X100_3_065]  261.07 70.98 180 top
Q1402  L2N7002WT1G  [TSSOT323_200X125X100_3_065]  242.6 91.04 270 top
Q1950  L2N7002WT1G  [TSSOT323_200X125X100_3_065]  295.94 95.87 180 top
Q2971  FDC638APZ  [TSOT_290X160X110_6_095]  295.38 120.64 0 top
Q4100  BSS138LT1  [TSSOT23_292X130X111_3_095]  173.39 146.42 180 top
Q4101  L2N7002WT1G  [TSSOT323_200X125X100_3_065]  176.44 146.42 0 top
Q4102  MMBT4401  [TSOT23_290X130X110_3_096]  131.6 144.77 0 top
Q4300  L2N7002DW1T1G  [TSSC88_200X125X110_6_065-2]  117.63 155.69 270 bottom
Q4501  L2N7002WT1G  [TSSOT323_200X125X100_3_065]  223.58 82.54 180 top
Q4505  DIODES_DMG3414U_7  [TSSOT23_290X130X120_3_095]  161.58 68.18 180 bottom
Q4700  L2N7002WT1G  [TSSOT323_200X125X100_3_065]  166.15 68.18 180 bottom
Q4752  L2N7002DW1T1G  [TSSC88_200X125X110_6_065-2]  151.24 84.73 270 bottom
Q4753  L2N7002DW1T1G  [TSSC88_200X125X110_6_065-2]  146.46 85.08 270 bottom
Q4754  LES_LBSS84LT1G_SOT23_3P  [TSSOT23_292X130X111_3_095]  156.62 109.71 270 top
Q4755  LES_LBSS84LT1G_SOT23_3P  [TSSOT23_292X130X111_3_095]  154.08 107.43 270 top
Q4756  L2N7002WT1G  [TSSOT323_200X125X100_3_065]  159.93 109.84 270 top
Q4759  L2N7002DW1T1G  [TSSC88_200X125X110_6_065-2]  151.29 87.74 270 bottom
Q4831  L2N7002WT1G  [TSSOT323_200X125X100_3_065]  147.3 99.93 90 bottom
Q4920  L2N7002DW1T1G  [TSSC88_200X125X110_6_065-2]  225.08 92.31 90 top
Q4921  L2N7002DW1T1G  [TSSC88_200X125X110_6_065-2]  228.12 92.31 90 top
Q4926  L2N7002DW1T1G  [TSSC88_200X125X110_6_065-2]  240.32 83.55 0 top
Q4942  L2N7002DW1T1G  [TSSC88_200X125X110_6_065-2]  163.56 72.17 180 bottom
Q5000  LMBT3904LT1G  [TSSOT23_292X130X111_3_096]  192.85 132.07 0 bottom
Q5301  L2N7002WT1G  [TSSOT323_200X125X100_3_065]  276.69 80.12 90 bottom
Q5314  L2N7002DW1T1G  [TSSC88_200X125X110_6_065-2]  146.46 87.62 270 bottom
Q5401  L2N7002WT1G  [TSSOT323_200X125X100_3_065]  261.14 75.93 180 top
Q6000  FDMC8884  [MOSFET_300X300X112_8_065]  270.8 120.76 0 bottom
Q6001  FDMC7692S  [MOSFET_300X300X112_8_065]  274.99 120.87 270 bottom
Q6009  L2N7002DW1T1G  [TSSC88_200X125X110_6_065-2]  303.94 146.8 90 top
Q6010  ALPHA_AON7403L_DFN_8P  [MOSFET_300X300X112_8_065]  296.45 140.7 90 top
Q6011  RQ3E080BNFU7TB  [MOSFET_300X300X112_8_065]  292.05 140.67 90 top
Q6012  ALPHA_AON7403L_DFN_8P  [MOSFET_300X300X112_8_065]  287.56 142.35 90 top
Q6900  PMBT3906  [TSOT23_290X130X110_3_095]  292.39 99.43 180 top
Q6901  LMBT3904LT1G  [TSSOT23_292X130X111_3_096]  61.88 88.89 180 top
Q6902  LES_LBSS84LT1G_SOT23_3P  [TSSOT23_292X130X111_3_095]  58.07 88.76 180 top
Q6903  PMBT3906  [TSOT23_290X130X110_3_095]  58.45 84.69 180 top
Q6998  L2N7002WT1G  [TSSOT323_200X125X100_3_065]  287.43 99.05 180 top
Q7002  L2N7002WT1G  [TSSOT323_200X125X100_3_065]  309.66 119.87 90 top
Q7050  ALPHA_AO6424L_TSOP_6P  [TSOP_290X160X125_6_095]  116.11 86.73 0 bottom
Q7051  L2N7002DW1T1G  [TSSC88_200X125X110_6_065-2]  118.9 88.76 0 bottom
Q7056  L2N7002DW1T1G  [TSSC88_200X125X110_6_065-2]  299.46 119.51 180 top
Q7100  ALPHA_AO6424L_TSOP_6P  [TSOP_290X160X125_6_095]  300.39 111.62 270 top
Q7101  L2N7002WT1G  [TSSOT323_200X125X100_3_065]  303.56 107.43 90 top
Q7150  L2N7002DW1T1G  [TSSC88_200X125X110_6_065-2]  123.48 89.39 0 bottom
Q7151  ALPHA_AO6424L_TSOP_6P  [TSOP_290X160X125_6_095]  133.26 82.92 0 bottom
Q7152  L2N7002WT1G  [TSSOT323_200X125X100_3_065]  120.68 93.25 0 bottom
Q7153  RQ3E150BNFU7TB  [MOSFET_300X300X112_8_065]  134.27 86.98 270 bottom
Q7154  L2N7002WT1G  [TSSOT323_200X125X100_3_065]  126.52 89.9 0 bottom
Q7155  L2N7002WT1G  [TSSOT323_200X125X100_3_065]  168.18 146.67 0 top
Q7350  L2N7002DW1T1G  [TSSC88_200X125X110_6_065-2]  206.41 146.92 180 top
Q7351  RQ3E100BNFU7TB  [MOSFET_300X300X112_8_065]  304.32 115.17 90 top
Q7352  L2N7002WT1G  [TSSOT323_200X125X100_3_065]  104.55 88.76 180 bottom
Q7353  RQ3E100BNFU7TB  [MOSFET_300X300X112_8_065]  112.3 86.73 90 bottom
Q7355  L2N7002WT1G  [TSSOT323_200X125X100_3_065]  305.98 119.87 270 top
Q9031  L2N7002WT1G  [TSSOT323_200X125X100_3_065]  72.42 139.18 90 top
Q9032  L2N7002DW1T1G  [TSSC88_200X125X110_6_065-2]  72.8 123.94 270 top
R100  47_5%_2  [RSC_100X050X040_2]  287.18 120 270 top
R101  100K_5%_2  [RSC_100X050X040_2]  286.29 120 270 top
R103  1K_5%_2  [RSC_100X050X040_2]  286.67 116.95 0 top
R113  47K_5%_2  [RSC_100X050X040_2]  127.41 85.58 90 bottom
R115  270_5%_2  [RSC_100X050X040_2]  310.29 150.99 0 top
R118  47K_5%_2  [RSC_100X050X040_2]  125.09 82.37 90 bottom
R124  10K_5%_2  [RSC_100X050X040_2]  311.69 150.48 90 top
R126  270_5%_2  [RSC_100X050X040_2]  307.25 145.02 0 top
R127  0_5%_2  [RSC_100X050X040_2]  281.08 117.46 90 top
R130  10K_5%_2  [RSC_100X050X040_2]  307.25 144.13 180 top
R135  47K_5%_2_DY  [RSC_100X050X040_2]  286.67 116.06 0 top
R136  330K_5%_2_DY  [RSC_100X050X040_2]  286.67 117.84 180 top
R300  300_5%_2  [RSC_100X050X040_2]  281.72 98.03 180 top
R301  1K_5%_2  [RSC_100X050X040_2]  281.72 95.11 0 top
R302  300_5%_2  [RSC_100X050X040_2]  281.72 96.12 180 top
R303  10K_5%_2_DY  [RSC_100X050X040_2]  262.54 90.03 270 top
R304  100K_5%_2_DY  [RSC_100X050X040_2]  258.51 100.4 180 top
R305  100K_5%_2_DY  [RSC_100X050X040_2]  254.41 103.36 180 top
R306  2.2K_5%_2  [RSC_100X050X040_2]  258.48 104.13 180 top
R307  2.2K_5%_2  [RSC_100X050X040_2]  256.83 103.11 180 top
R309  10K_5%_2  [RSC_100X050X040_2]  258.48 107.81 180 top
R310  2.2K_5%_2  [RSC_100X050X040_2]  144.05 88.38 180 bottom
R311  2.2K_5%_2  [RSC_100X050X040_2]  144.05 86.85 180 bottom
R312  10K_5%_2  [RSC_100X050X040_2]  279.31 113.9 90 top
R313  10K_5%_2  [RSC_100X050X040_2]  278.42 113.9 90 top
R314  100K_5%_2  [RSC_100X050X040_2]  281.08 113.9 90 top
R315  300_5%_2  [RSC_100X050X040_2]  281.72 100.06 180 top
R316  300_5%_2  [RSC_100X050X040_2]  281.72 99.05 180 top
R317  100K_5%_2  [RSC_100X050X040_2]  283.62 112.76 0 top
R318  10K_5%_2_DY  [RSC_100X050X040_2]  258.51 103.07 180 top
R319  short_0402_5  [RSC_100X050X040_2_SHORT]  281.72 97.01 180 top
R320  100K_5%_2  [RSC_100X050X040_2]  268.26 113.9 90 top
R321  20K_5%_2  [RSC_100X050X040_2]  283.62 110.09 0 top
R322  10K_5%_2  [RSC_100X050X040_2]  258.51 101.29 180 top
R323  0_5%_2_DY  [RSC_100X050X040_2]  279.69 90.66 90 top
R324  10K_5%_2  [RSC_100X050X040_2]  258.51 102.18 180 top
R325  10K_5%_2  [RSC_100X050X040_2]  270.16 113.9 270 top
R326  100K_5%_2  [RSC_100X050X040_2]  258.48 108.7 180 top
R327  100K_5%_2  [RSC_100X050X040_2]  256.83 104.13 0 top
R328  43_5%_2  [RSC_100X050X040_2]  269.27 113.9 90 top
R329  10K_5%_2  [RSC_100X050X040_2]  266.48 113.9 90 top
R330  10K_5%_2  [RSC_100X050X040_2]  265.59 113.9 90 top
R331  4.7K_5%_2  [RSC_100X050X040_2]  146.08 80 270 bottom
R332  100K_5%_2  [RSC_100X050X040_2]  254.03 101.84 180 top
R333  33_5%_2  [RSC_100X050X040_2]  280.82 103.12 0 top
R334  0_5%_2  [RSC_100X050X040_2]  279.31 92.64 0 top
R335  short_0402_5  [RSC_100X050X040_2_SHORT]  143.29 79.87 0 bottom
R336  15_5%_2_DY  [RSC_100X050X040_2]  143.29 82.54 0 bottom
R337  15_5%_2_DY  [RSC_100X050X040_2]  143.29 80.76 0 bottom
R338  15_5%_2_DY  [RSC_100X050X040_2]  143.29 83.42 0 bottom
R339  15_5%_2_DY  [RSC_100X050X040_2]  143.29 81.65 0 bottom
R340  10K_5%_2_DY  [RSC_100X050X040_2]  162.97 97.39 180 bottom
R341  10K_5%_2_DY  [RSC_100X050X040_2]  263.56 90.03 90 top
R342  10K_5%_2_DY  [RSC_100X050X040_2]  271.05 113.9 90 top
R343  short_0402_15  [RSC_100X050X040_2_15_SHORT]  135.54 70.47 180 top
R344  3.3K_5%_2  [RSC_100X050X040_2]  232.06 59.17 90 bottom
R345  0_5%_2_DY  [RSC_100X050X040_2]  232.06 57.52 270 bottom
R346  3.3K_5%_2  [RSC_100X050X040_2]  230.28 59.17 270 bottom
R347  short_0402_5  [RSC_100X050X040_2_SHORT]  258.86 110.48 180 top
R351  4.7K_5%_2  [RSC_100X050X040_2]  292.13 97.14 180 top
R352  short_0402_5  [RSC_100X050X040_2_SHORT]  258.48 109.59 180 top
R355  4.7K_5%_2  [RSC_100X050X040_2]  232.95 59.17 270 bottom
R356  10K_5%_2_DY  [RSC_100X050X040_2]  258.48 105.03 180 top
R360  0_5%_2  [RSC_100X050X040_2]  260.51 85.2 90 top
R361  0_5%_2  [RSC_100X050X040_2]  261.6 90.03 90 top
R362  33_5%_2  [RSC_100X050X040_2]  264.19 92.06 90 top
R363  10K_5%_2  [RSC_100X050X040_2]  298.86 132.57 90 top
R365  33_5%_2  [RSC_100X050X040_2]  254.67 95.24 180 top
R366  33_5%_2  [RSC_100X050X040_2]  252.76 95.74 270 top
R367  33_5%_2  [RSC_100X050X040_2]  151.42 82.15 180 bottom
R368  3.3K_5%_2  [RSC_100X050X040_2]  146.34 65.26 270 bottom
R369  3.3K_5%_2  [RSC_100X050X040_2]  146.97 80 90 bottom
R370  0_5%_2_DY  [RSC_100X050X040_2]  147.86 80 90 bottom
R371  100K_5%_2  [RSC_100X050X040_2]  282.99 103.87 0 top
R372  short_0603_25  [RSC_160X080X080_2_25_SHORT]  111.54 147.69 180 top
R373  10K_5%_2  [RSC_100X050X040_2]  263.3 92.06 270 top
R382  short_0402_5  [RSC_100X050X040_2_SHORT]  275.24 113.9 90 top
R383  10K_5%_2  [RSC_100X050X040_2]  269.91 87.87 90 top
R385  10K_5%_2  [RSC_100X050X040_2]  281.72 93.33 180 top
R386  10K_5%_2  [RSC_100X050X040_2]  276.13 91.43 270 top
R387  10K_5%_2  [RSC_100X050X040_2]  283.62 110.98 0 top
R388  10K_5%_2  [RSC_100X050X040_2]  283.62 111.87 0 top
R390  33_5%_2  [RSC_100X050X040_2]  234.09 59.17 270 bottom
R391  10K_5%_2  [RSC_100X050X040_2]  254.41 104.25 180 top
R392  270_5%_2  [RSC_100X050X040_2]  266.22 91.04 90 top
R393  270_5%_2  [RSC_100X050X040_2]  264.07 86.73 270 top
R394  270_5%_2  [RSC_100X050X040_2]  266.22 89.39 90 top
R396  33_5%_2  [RSC_100X050X040_2]  254.67 96.12 180 top
R398  1K_5%_2  [RSC_100X050X040_2]  269.27 107.43 0 bottom
R400  RSC_0402_DY  [RSC_100X050X040_2]  295.56 103.62 0 top
R401  3.01K_1%_2  [RSC_100X050X040_2]  296.83 107.05 0 top
R402  470_5%_2  [RSC_100X050X040_2]  296.2 114.03 180 top
R403  470_5%_2  [RSC_100X050X040_2]  294.42 115.43 270 top
R404  1K_5%_2  [RSC_100X050X040_2]  293.15 116.19 90 top
R405  10K_5%_2_DY  [RSC_100X050X040_2]  288.7 103.36 270 top
R407  4.7K_5%_2  [RSC_100X050X040_2]  287.43 104.76 90 top
R470  75_1%_2  [RSC_100X050X040_2]  313.47 97.39 180 top
R471  75_1%_2  [RSC_100X050X040_2]  313.47 96.51 180 top
R472  75_1%_2  [RSC_100X050X040_2]  313.47 92.31 180 top
R473  75_1%_2  [RSC_100X050X040_2]  313.47 91.43 180 top
R485  100K_5%_2  [RSC_100X050X040_2]  310.17 106.16 90 top
R487  10K_5%_2  [RSC_100X050X040_2]  295.36 117.08 90 top
R488  20K_5%_2  [RSC_100X050X040_2]  295.36 115.43 90 top
R489  2.2K_5%_2_DY  [RSC_100X050X040_2]  294.04 117.08 90 top
R499  short_0402_15  [RSC_100X050X040_2_15_SHORT]  289.59 103.36 90 top
R501  0_5%_2_DY  [RSC_100X050X040_2]  296.27 59.95 0 top
R502  20K_1%_2  [RSC_100X050X040_2]  304.71 54.6 270 top
R503  100_5%_2  [RSC_100X050X040_2]  280.19 52.31 180 bottom
R504  6.2K_1%_2  [RSC_100X050X040_2]  301.53 54.85 90 top
R505  6.2K_1%_2  [RSC_100X050X040_2]  300.64 54.85 90 top
R506  3.48K_1%_2  [RSC_100X050X040_2]  300.64 53.2 270 top
R507  3.48K_1%_2  [RSC_100X050X040_2]  301.53 53.2 270 top
R509  0_5%_2_DY  [RSC_100X050X040_2]  290.35 62.85 90 top
R510  20K_5%_2  [RSC_100X050X040_2]  293.66 58.61 90 top
R511  0_5%_2_DY  [RSC_100X050X040_2]  290.86 61.58 0 top
R513  47K_5%_2  [RSC_100X050X040_2]  292.77 58.61 270 top
R514  33_5%_2  [RSC_100X050X040_2]  296.27 59.07 180 top
R515  39.2K_1%_2  [RSC_100X050X040_2]  293.02 57.14 180 top
R516  33_5%_2  [RSC_100X050X040_2]  296.32 63.87 180 top
R517  10K_5%_2  [RSC_100X050X040_2]  288.32 62.85 90 top
R520  0_5%_5  [RSC_200X125X115_2]  310.93 67.04 270 top
R521  0_5%_5  [RSC_200X125X115_2]  291.12 58.28 270 bottom
R528  20K_1%_2  [RSC_100X050X040_2]  298.36 55.87 270 top
R529  100K_5%_2  [RSC_100X050X040_2]  295.05 54.09 90 top
R530  100K_5%_2  [RSC_100X050X040_2]  296.96 52.94 180 top
R531  5.1K_1%_2  [RSC_100X050X040_2]  298.36 53.33 270 top
R532  0_5%_2  [RSC_100X050X040_2]  308.39 57.01 270 top
R533  0_5%_2  [RSC_100X050X040_2]  291.37 62.85 90 top
R534  0_5%_2  [RSC_100X050X040_2]  299.37 67.93 90 top
R535  0_5%_2  [RSC_100X050X040_2]  300.26 67.93 90 top
R536  0_5%_2  [RSC_100X050X040_2]  301.15 67.93 90 top
R537  0_5%_2  [RSC_100X050X040_2]  302.04 67.93 90 top
R550  2.2K_5%_2  [RSC_100X050X040_2]  311.69 72.76 0 top
R551  2.2K_5%_2  [RSC_100X050X040_2]  311.69 73.65 0 top
R552  39K_1%_2  [RSC_100X050X040_2]  306.23 69.71 90 top
R553  0_5%_2  [RSC_100X050X040_2]  305.09 70.6 270 top
R556  0_5%_2  [RSC_100X050X040_2]  308.77 68.06 270 top
R557  39K_1%_2  [RSC_100X050X040_2]  309.66 68.06 90 top
R558  2.2K_5%_2  [RSC_100X050X040_2]  309.66 57.39 180 top
R559  2.2K_5%_2  [RSC_100X050X040_2]  309.66 56.5 180 top
R560  22K_5%_2_DY  [RSC_100X050X040_2]  308.26 62.6 0 top
R561  0_5%_2  [RSC_100X050X040_2]  306.48 62.34 180 top
R562  0_5%_2  [RSC_100X050X040_2]  306.48 61.45 180 top
R563  0_5%_2  [RSC_100X050X040_2]  306.61 60.56 180 top
R564  0_5%_2  [RSC_100X050X040_2]  306.61 58.53 180 top
R565  22K_5%_2_DY  [RSC_100X050X040_2]  308.26 58.41 0 top
R566  30_5%_2  [RSC_100X050X040_2]  307.25 77.2 90 top
R567  30_5%_2  [RSC_100X050X040_2]  310.55 77.2 90 top
R568  30_5%_2  [RSC_100X050X040_2]  312.58 55.23 180 top
R569  30_5%_2  [RSC_100X050X040_2]  309.66 55.61 180 top
R570  10K_5%_2  [RSC_100X050X040_2]  311.69 71.87 0 top
R571  39K_1%_2  [RSC_100X050X040_2]  307.25 69.33 90 top
R572  39K_1%_2  [RSC_100X050X040_2]  308.26 69.71 90 top
R602  2.2K_5%_2  [RSC_100X050X040_2]  305.98 53.33 180 top
R603  100K_5%_2  [RSC_100X050X040_2]  293.02 53.07 180 top
R604  22K_5%_2  [RSC_100X050X040_2]  305.98 52.44 180 top
R605  22K_5%_2  [RSC_100X050X040_2]  307.25 52.94 90 top
R612  0_5%_2  [RSC_100X050X040_2]  285.66 52.82 0 bottom
R617  0_5%_2  [RSC_100X050X040_2]  285.66 55.61 180 bottom
R618  100K_5%_2_DY  [RSC_100X050X040_2]  293.38 54.15 0 bottom
R619  100K_5%_2_DY  [RSC_100X050X040_2]  292.87 57.07 0 bottom
R620  1K_5%_3  [RSC_160X080X055_2]  290.1 56.25 180 bottom
R640  10K_5%_2  [RSC_100X050X040_2]  198.01 42.91 180 bottom
R641  10K_5%_2  [RSC_100X050X040_2]  243.47 47.61 180 bottom
R800  short_0402_15  [RSC_100X050X040_2_15_SHORT]  285.53 71.49 180 top
R801  6.2K_1%_2  [RSC_100X050X040_2]  284.77 72.76 0 top
R802  10K_5%_2  [RSC_100X050X040_2]  297.47 72.12 90 top
R803  47K_5%_2  [RSC_100X050X040_2]  289.59 59.29 90 bottom
R808  10K_5%_2  [RSC_100X050X040_2]  295.43 78.85 180 top
R809  10K_5%_2  [RSC_100X050X040_2]  290.1 77.07 90 bottom
R810  100K_5%_2  [RSC_100X050X040_2]  291.24 77.07 270 bottom
R811  10K_5%_2  [RSC_100X050X040_2]  284.26 62.22 0 bottom
R1000  0_5%_2_DY  [RSC_100X050X040_2]  247.17 99.17 0 top
R1001  0_5%_2_DY  [RSC_100X050X040_2]  243.75 99.17 0 top
R1006  short_0402_5  [RSC_100X050X040_2_SHORT]  239.17 107.55 270 top
R1007  47K_5%_2_DY  [RSC_100X050X040_2]  230.16 104.13 90 top
R1008  47K_5%_2_DY  [RSC_100X050X040_2]  230.28 107.05 270 top
R1010  0_5%_2_DY  [RSC_100X050X040_2]  239.17 104.25 270 top
R1300  100K_5%_2  [RSC_100X050X040_2]  306.99 122.67 0 top
R1301  220K_5%_2  [RSC_100X050X040_2]  304.32 131.18 270 top
R1302  10K_5%_2  [RSC_100X050X040_2]  303.18 131.18 270 top
R1304  10K_5%_2  [RSC_100X050X040_2]  310.55 127.75 270 top
R1306  10K_5%_2_DY  [RSC_100X050X040_2]  313.21 112.89 0 top
R1307  100K_5%_2  [RSC_100X050X040_2]  313.21 124.19 180 top
R1310  0_5%_2_DY  [RSC_100X050X040_2]  315.75 126.6 270 top
R1311  short_0402_5  [RSC_100X050X040_2_SHORT]  302.93 128.64 90 top
R1315  10K_5%_2  [RSC_100X050X040_2]  313.21 125.08 0 top
R1403  220K_5%_2_DY  [RSC_100X050X040_2]  262.41 80.5 90 bottom
R1404  10K_5%_2  [RSC_100X050X040_2]  261.14 80.88 0 bottom
R1405  0_5%_2_DY  [RSC_100X050X040_2]  245.27 75.3 180 bottom
R1407  10K_5%_2_DY  [RSC_100X050X040_2]  257.33 73.65 180 bottom
R1408  10K_5%_2  [RSC_100X050X040_2]  255.43 53.96 270 bottom
R1409  short_0402_5  [RSC_100X050X040_2_SHORT]  245.14 66.66 0 bottom
R1410  0_5%_2_DY  [RSC_100X050X040_2]  245.52 58.66 0 bottom
R1417  short_0402_5  [RSC_100X050X040_2_SHORT]  258.73 74.66 90 bottom
R1451  47K_5%_2_DY  [RSC_100X050X040_2]  249.33 80.63 270 top
R1452  100K_5%_2_DY  [RSC_100X050X040_2]  247.3 80.63 270 top
R1952  0_5%_2_DY  [RSC_100X050X040_2]  306.99 102.6 0 bottom
R1953  0_5%_2_DY  [RSC_100X050X040_2]  296.45 98.16 0 top
R1955  10K_5%_2  [RSC_100X050X040_2]  296.2 93.71 0 top
R1956  RSC_0603_DY  [RSC_160X080X080_2]  296.2 91.55 180 top
R2200  10K_5%_2  [RSC_100X050X040_2]  283.24 56.88 180 bottom
R2201  10K_5%_2  [RSC_100X050X040_2]  164.24 73.39 180 top
R2202  short_0402_15  [RSC_100X050X040_2_15_SHORT]  281.9 53.07 270 top
R2203  0_5%_2_DY  [RSC_100X050X040_2]  284 55.87 180 bottom
R2204  0_5%_2_DY  [RSC_100X050X040_2]  164.24 72.5 180 top
R2205  short_0402_5  [RSC_100X050X040_2_SHORT]  175.8 77.96 90 top
R2500  1M_5%_2_DY  [RSC_100X050X040_2]  267.24 54.85 270 top
R2511  20K_5%_2  [RSC_100X050X040_2]  42.58 84.19 180 top
R2512  17.8K_1%_2  [RSC_100X050X040_2]  44.36 84.19 180 top
R2514  0_5%_2_DY  [RSC_100X050X040_2]  46.9 80.5 180 bottom
R2515  10K_5%_2  [RSC_100X050X040_2]  46.9 79.61 0 bottom
R2553  12K_1%_2  [RSC_100X050X040_2]  268.81 52.82 90 top
R2554  10K_5%_2  [RSC_100X050X040_2]  265.84 65.01 180 top
R2555  10K_5%_2  [RSC_100X050X040_2]  263.3 57.64 180 top
R2556  0_5%_2_DY  [RSC_100X050X040_2]  272.96 69.58 90 top
R2557  0_5%_2_DY  [RSC_100X050X040_2]  277.02 68.44 270 top
R2558  10K_5%_2  [RSC_100X050X040_2]  272.96 71.23 270 top
R2559  10K_5%_2  [RSC_100X050X040_2]  275.24 66.91 90 top
R2560  10K_5%_2  [RSC_100X050X040_2]  266.73 69.58 270 top
R2561  10K_5%_2_DY  [RSC_100X050X040_2]  268.51 69.58 270 top
R2562  10K_5%_2  [RSC_100X050X040_2]  267.62 69.58 90 top
R2563  10K_5%_2  [RSC_100X050X040_2]  268.13 71.61 270 top
R2564  10K_5%_2  [RSC_100X050X040_2]  270.03 71.61 270 top
R2565  10K_5%_2_DY  [RSC_100X050X040_2]  279.31 62.85 90 bottom
R2566  10K_5%_2_DY  [RSC_100X050X040_2]  281.72 60.44 0 bottom
R2567  8.2K_5%_2  [RSC_100X050X040_2]  278.87 63.31 0 top
R2568  10K_5%_2_DY  [RSC_100X050X040_2]  261.4 63.31 180 top
R2569  10K_5%_2_DY  [RSC_100X050X040_2]  263.68 62.47 0 top
R2570  10K_5%_2_DY  [RSC_100X050X040_2]  261.4 52.44 90 bottom
R2571  0_5%_2_DY  [RSC_100X050X040_2]  263.68 63.36 180 top
R2572  0_5%_2_DY  [RSC_100X050X040_2]  257.46 66.71 270 bottom
R2573  10K_5%_2  [RSC_100X050X040_2]  272.57 62.6 90 bottom
R2574  10K_5%_2  [RSC_100X050X040_2]  269.4 69.58 90 top
R2575  10K_5%_2  [RSC_100X050X040_2]  260.51 52.44 90 bottom
R2576  8.2K_5%_2_DY  [RSC_100X050X040_2]  273.59 62.85 270 bottom
R2580  10K_5%_2_DY  [RSC_100X050X040_2]  258.6 52.44 90 bottom
R2581  10K_5%_2_DY  [RSC_100X050X040_2]  260.38 66.79 270 bottom
R2585  100_5%_2  [RSC_100X050X040_2]  268.64 66.66 90 top
R2590  10K_5%_2  [RSC_100X050X040_2]  258.35 66.71 270 bottom
R2591  10K_5%_2_DY  [RSC_100X050X040_2]  259.49 52.44 90 bottom
R2592  short_0402_5  [RSC_100X050X040_2_SHORT]  261.4 64.37 0 top
R2593  0_5%_2_DY  [RSC_100X050X040_2]  270.42 67.42 0 top
R2594  0_5%_2_DY  [RSC_100X050X040_2]  263.68 64.37 0 top
R2950  46.4K_1%_2  [RSC_100X050X040_2]  249.84 108.32 90 top
R2951  35.7K_1%_2  [RSC_100X050X040_2]  250.73 108.32 90 top
R2952  1K_1%_2  [RSC_100X050X040_2]  257.02 114.64 90 top
R2953  1M_5%_2  [RSC_100X050X040_2]  252.13 113.02 90 top
R2954  3.3K_5%_2  [RSC_100X050X040_2]  253.02 113.02 90 top
R2955  10K_5%_2  [RSC_100X050X040_2]  248.95 108.32 90 top
R2956  1M_5%_2  [RSC_100X050X040_2]  255.19 114.64 90 top
R2957  3.3K_5%_2  [RSC_100X050X040_2]  256.11 114.64 270 top
R2958  13K_1%_2  [RSC_100X050X040_2]  245.14 109.08 90 top
R2959  41.2K_1%_2  [RSC_100X050X040_2]  246.03 109.08 90 top
R2960  0_5%_2_DY  [RSC_100X050X040_2]  246.92 109.08 90 top
R2970  330K_5%_2  [RSC_100X050X040_2]  297.68 120.02 90 top
R2971  47K_5%_2  [RSC_100X050X040_2]  298.71 121.74 270 top
R2972  47_5%_2  [RSC_100X050X040_2]  293.28 119.75 270 top
R3001  100_5%_2  [RSC_100X050X040_2]  102.78 113.14 0 top
R3003  100K_5%_2  [RSC_100X050X040_2]  105.06 113.14 180 top
R3008  100K_5%_2  [RSC_100X050X040_2]  107.81 116.76 180 top
R3009  2K_5%_2  [RSC_100X050X040_2]  109.44 116.76 0 top
R3013  0_5%_2_DY  [RSC_100X050X040_2]  109.38 121.91 90 top
R3021  100K_5%_2  [RSC_100X050X040_2]  106.49 116.28 90 top
R3051  75_1%_2  [RSC_100X050X040_2]  40.42 65.01 270 top
R3052  75_1%_2  [RSC_100X050X040_2]  40.42 67.3 270 top
R3053  75_1%_2  [RSC_100X050X040_2]  40.42 69.71 270 top
R3059  4.7K_5%_2  [RSC_100X050X040_2]  37.75 66.79 270 bottom
R3060  4.7K_5%_2  [RSC_100X050X040_2]  37.37 76.44 90 bottom
R3061  10K_5%_2  [RSC_100X050X040_2]  88.41 90.96 180 bottom
R3062  0_5%_2_DY  [RSC_100X050X040_2]  88.41 92.79 180 bottom
R3063  0_5%_2  [RSC_100X050X040_2]  87.17 89.99 180 bottom
R3064  0_5%_2_DY  [RSC_100X050X040_2]  77.56 87.66 0 top
R3065  12K_5%_DY  [RSC_100X050X035_2]  86.63 91.44 270 bottom
R3066  33_5%_2  [RSC_100X050X040_2]  84.09 82.04 0 top
R3067  10K_5%_2_DY  [RSC_100X050X040_2]  77.56 85.83 180 top
R3068  1.2K_1%_2  [RSC_100X050X040_2]  88.55 82.54 270 top
R3069  33_5%_2  [RSC_100X050X040_2]  82.41 82.1 0 top
R3071  100K_5%_2_DY  [RSC_100X050X040_2]  79.79 89.39 0 top
R3074  10K_5%_2_DY  [RSC_100X050X040_2]  89.14 88.95 270 bottom
R3075  0_5%_2  [RSC_100X050X040_2]  91.23 90.43 180 bottom
